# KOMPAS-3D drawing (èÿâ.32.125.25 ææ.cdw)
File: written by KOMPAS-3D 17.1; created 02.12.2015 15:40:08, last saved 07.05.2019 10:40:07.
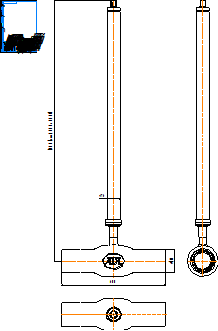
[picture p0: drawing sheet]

Sheet 1: A4, portrait

Title block, sheet 1: name: КШГ.32.125.25 СС; material: Внимание! Данный продукт является объектом авторского права ООО «Торговый Дом АДЛ». / Запрещается изменение, копирование, распространение / (в том числе путем копирования на другие сайты и ресурсы в Интернете) / или любое иное использование информации и объектов без предварительного / согласия правообладателя (ООО «Торговый Дом АДЛ»).; sheets: 1; organisation: ООО "Торговый дом АДЛ"; sheet format: A4; stored path: C:\Users\kka\KOMPAS_Work\Модели кранов для исследований\DN50\С удлинением\КШГ.32.050.40 СС ГЧ _ Шаровой кран БИВАЛ Ду50 Ру4 МПа редуцированный под приварку, с удлинением штока H=1100.cdw; drawn by: Климкович К.А.; drawn by, date: 02.12.15

Views: Вид 1, Проекционный вид 2, Проекционный вид 3
Referenced files in C:\Users\kka\KOMPAS_Work\Модели кранов для исследований\DN80\С удлинением\: КШТ.22.080.25 СС.a3d, КШГ.35.065.25 СС.a3d!КШГ.45.065.10 СС!Деталь (локальная).m3d
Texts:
  Klimkovich
  ADL
  (от 425 до 5000)
Dimensions and other numbers on the sheet: 600; 1500; 133; 76; 1:1; 1; 02.12.15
